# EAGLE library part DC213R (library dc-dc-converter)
DC-DC CONVERTER
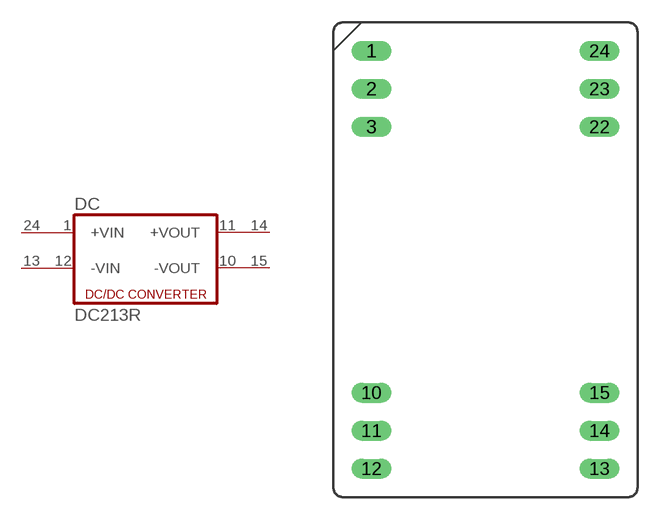
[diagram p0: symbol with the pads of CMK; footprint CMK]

Designator prefix DC

## DC213R (OC_FARNELL: unknown; OC_NEWARK: unknown)  [CMK]
1  +VIN  pas
10  -VOUT  pas
11  +VOUT  pas
12  -VIN  pas
13  -VIN1  pas
14  +VOUT1  pas
15  -VOUT1  pas
24  +VIN1  pas

## Footprint CMK (pad centres in mm)
DC-DC CONVERTER
drill 0.813 long: 1 -7.62,13.97; 2 -7.62,11.43; 3 -7.62,8.89; 10 -7.62,-8.89; 11 -7.62,-11.43; 12 -7.62,-13.97; 13 7.62,-13.97; 14 7.62,-11.43; 15 7.62,-8.89; 22 7.62,8.89; 23 7.62,11.43; 24 7.62,13.97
